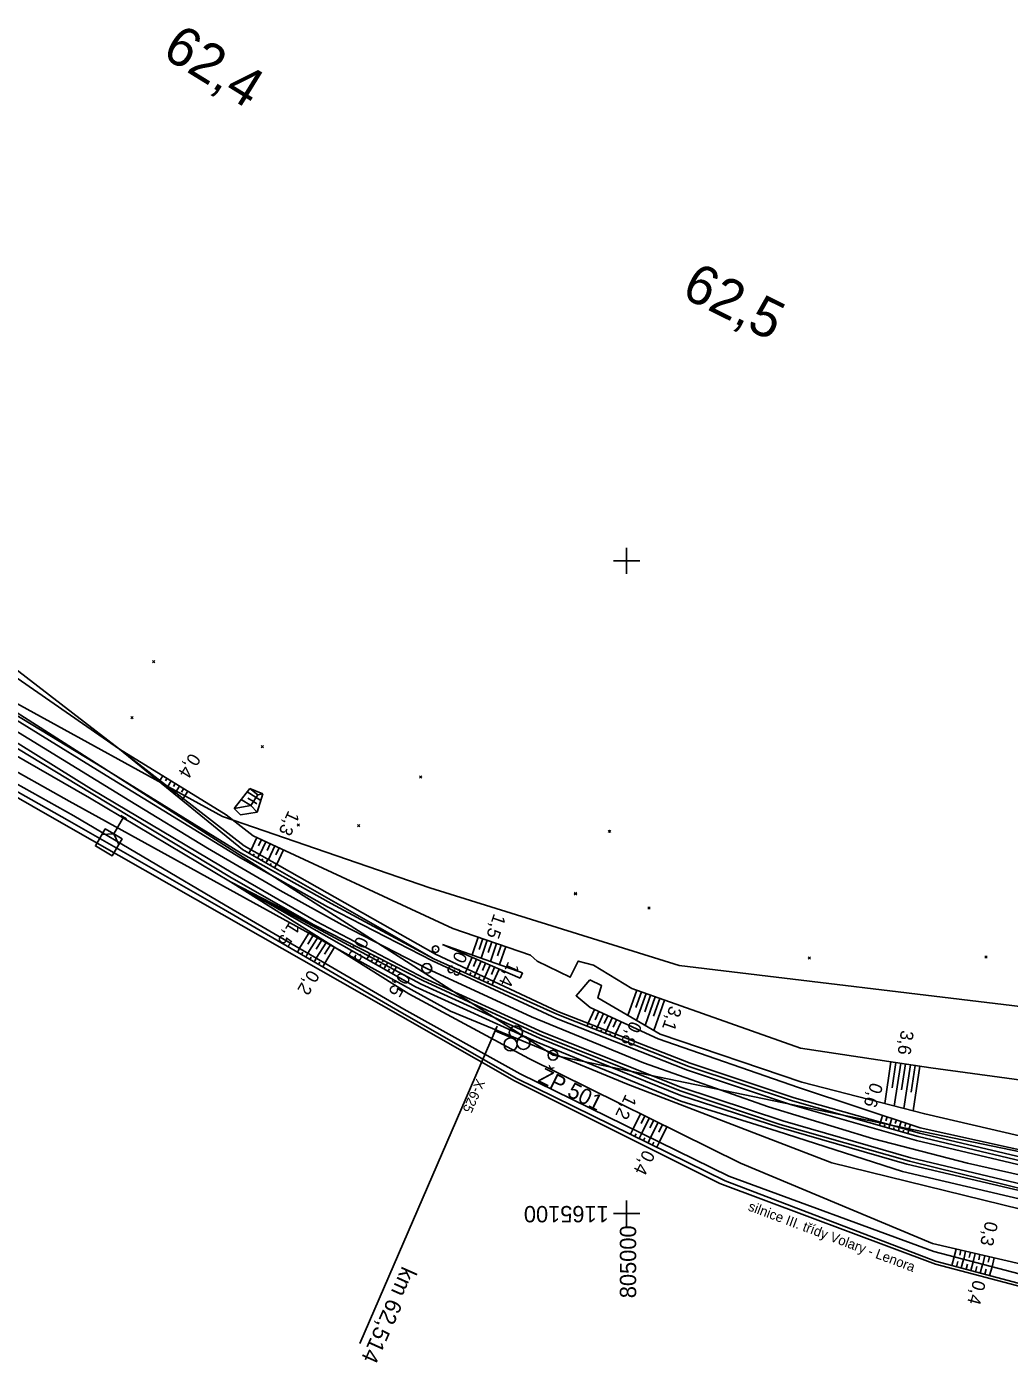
# Model space of a CAD drawing. Extents: x -805636 to -804553, y -1165340 to -1164656.
# Drawn here: x -805092 to -804941.3, y -1165124 to -1164918.2 of the extents above; entities that cross this region are included whole.
import ezdxf

# ---------------------------------------------------------------- set-up
doc = ezdxf.new("R2010")
doc.units = 0
for name, color, linetype in [('0381KM061-064P - Vrstva 1', 7, 'Continuous'), ('0381KM061-064P - Vrstva 4', 7, 'Continuous'), ('0381KM061-064P - Vrstva 48', 7, 'Continuous'), ('0381KM061-064P - Vrstva 49', 7, 'Continuous'), ('0381KM061-064P - Vrstva 51', 7, 'Continuous'), ('0381KM061-064P - Vrstva 7', 7, 'Continuous'), ('0381KM061-064P - Vrstva 8', 7, 'Continuous'), ('hran DP - hran DP', 7, 'Continuous'), ('krizky_1000 - souradnice', 7, 'Continuous'), ('krizky_1000 - Vrstva 1', 7, 'Continuous'), ('vyt_sit - polygon', 7, 'Continuous'), ('vyt_sit - stávající', 7, 'Continuous')]:
    doc.layers.add(name, color=color, linetype=linetype)

msp = doc.modelspace()

# ---------------------------------------------------------------- linework, layer by layer
at = {"layer": '0381KM061-064P - Vrstva 1'}
for points in [[(-805131.47, -1165002.7), (-805117.01, -1165011.6), (-805094.55, -1165025.46), (-805076.19, -1165036.77)], [(-805076.19, -1165036.77), (-805064.24, -1165044.04), (-805053.13, -1165050.53)], [(-805053.13, -1165050.53), (-805043.64, -1165055.76), (-805030.64, -1165062.45), (-805014.61, -1165069.88), (-804997.39, -1165076.92), (-804978.26, -1165083.66), (-804962.13, -1165088.54), (-804947.73, -1165092.28), (-804936.17, -1165094.91), (-804922.95, -1165097.46), (-804911.85, -1165099.22)]]:
    msp.add_lwpolyline(points, dxfattribs=at)
at = {"layer": '0381KM061-064P - Vrstva 4'}
for points in [[(-805257.4, -1164945.18), (-805227.5, -1164957.9), (-805205.55, -1164967.2), (-805161.7, -1164987.26), (-805121.4, -1165011.84), (-805082.08, -1165035.58)], [(-805257.21, -1164944.39), (-805227.21, -1164957.06), (-805205.17, -1164966.48), (-805161.59, -1164986.72), (-805120.84, -1165010.88), (-805082.03, -1165034.98)], [(-805187.57, -1164970.92), (-805160.12, -1164984.24), (-805119.58, -1165008.37), (-805080.47, -1165032.5)], [(-805187.4, -1164970.45), (-805159.98, -1164983.82), (-805119.44, -1165007.96), (-805080.11, -1165031.8)], [(-805080.11, -1165031.8), (-805059.18, -1165044.72), (-805045.31, -1165052.51), (-805029.54, -1165060.96), (-805010.72, -1165069.47), (-804990.45, -1165077.48), (-804974.57, -1165082.73), (-804955.28, -1165088.2), (-804932.96, -1165093.51), (-804912.39, -1165097.1), (-804892.28, -1165099.85)], [(-805080.47, -1165032.5), (-805059.19, -1165045.48), (-805045.86, -1165053.03), (-805029.76, -1165061.31), (-805010.76, -1165070.1), (-804990.66, -1165078.03), (-804974.85, -1165083.28), (-804955.57, -1165088.82), (-804933.31, -1165094.09), (-804912.36, -1165097.73), (-804892.37, -1165100.24)], [(-805082.08, -1165035.58), (-805060.58, -1165048.58), (-805047.98, -1165055.77), (-805031.23, -1165064.28), (-805013.07, -1165072.73), (-804991.62, -1165081.24), (-804976.47, -1165086.37), (-804956.64, -1165091.96), (-804934.05, -1165097.54), (-804913.13, -1165101.06), (-804892.22, -1165103.81)], [(-805082.03, -1165034.98), (-805060.37, -1165047.85), (-805047.54, -1165055.28), (-805031.06, -1165063.92), (-805012.89, -1165072.24), (-804991.69, -1165080.62), (-804976.05, -1165085.82), (-804956.42, -1165091.49), (-804933.87, -1165096.82), (-804912.82, -1165100.43), (-804892.24, -1165103.28)]]:
    msp.add_lwpolyline(points, dxfattribs=at)
at = {"layer": '0381KM061-064P - Vrstva 48'}
for p, q in [((-805071.7, -1165033.78), (-805071.58, -1165033.63)), ((-805071.12, -1165032.94), (-805071.56, -1165033.64)), ((-805070.48, -1165033.33), (-805070.72, -1165033.72)), ((-805069.84, -1165033.72), (-805070.36, -1165034.57)), ((-805071.12, -1165034.26), (-805071.05, -1165034.17)), ((-805070.54, -1165034.73), (-805070.39, -1165034.55)), ((-805069.96, -1165035.21), (-805069.88, -1165035.11)), ((-805069.21, -1165034.12), (-805069.49, -1165034.57)), ((-805069.38, -1165035.68), (-805069.2, -1165035.47)), ((-805068.57, -1165034.51), (-805069.17, -1165035.49)), ((-805067.93, -1165034.91), (-805068.25, -1165035.43)), ((-805067.29, -1165035.3), (-805067.98, -1165036.41)), ((-805058.16, -1165035.39), (-805056.82, -1165036.27)), ((-805068.8, -1165036.16), (-805068.71, -1165036.04)), ((-805068.22, -1165036.63), (-805068.02, -1165036.38)), ((-805059.08, -1165036.56), (-805057.62, -1165037.51)), ((-805058.06, -1165036.34), (-805057.22, -1165036.89)), ((-805056.69, -1165037.24), (-805057.22, -1165036.89)), ((-805056.11, -1165036.74), (-805056.82, -1165036.27)), ((-805056.69, -1165042.41), (-805057.55, -1165044.27)), ((-805056.01, -1165042.72), (-805056.45, -1165043.68)), ((-805055.32, -1165043.04), (-805056.24, -1165045.01)), ((-805054.64, -1165043.35), (-805055.11, -1165044.37)), ((-805053.96, -1165043.67), (-805054.93, -1165045.76)), ((-805053.28, -1165043.99), (-805053.78, -1165045.05)), ((-805057.91, -1165044.8), (-805057.59, -1165044.25)), ((-805057.26, -1165045.18), (-805057.1, -1165044.9)), ((-805056.61, -1165045.55), (-805056.29, -1165044.99)), ((-805055.96, -1165045.92), (-805055.8, -1165045.64)), ((-805055.31, -1165046.29), (-805054.98, -1165045.72)), ((-805052.6, -1165044.3), (-805053.62, -1165046.5)), ((-805054.65, -1165046.66), (-805054.49, -1165046.38)), ((-805054, -1165047.03), (-805053.68, -1165046.46)), ((-805050.18, -1165059.36), (-805048.58, -1165056.81)), ((-805048.9, -1165058.73), (-805047.94, -1165057.21)), ((-805048.89, -1165060.12), (-805047.31, -1165057.61)), ((-805047.61, -1165059.5), (-805046.68, -1165058.01)), ((-805047.59, -1165060.88), (-805046.04, -1165058.41)), ((-805023.71, -1165060.37), (-805022.78, -1165057.65)), ((-805022.63, -1165059.53), (-805022.07, -1165057.89)), ((-805022.3, -1165060.87), (-805021.36, -1165058.14)), ((-805021.22, -1165060.02), (-805020.66, -1165058.38)), ((-805020.89, -1165061.37), (-805019.95, -1165058.62)), ((-805050.16, -1165059.38), (-805050.49, -1165059.95)), ((-805049.64, -1165059.98), (-805049.84, -1165060.32)), ((-805048.86, -1165060.13), (-805049.19, -1165060.7)), ((-805046.33, -1165060.28), (-805045.41, -1165058.81)), ((-805046.29, -1165061.63), (-805044.77, -1165059.21)), ((-805039.53, -1165060.53), (-805039.82, -1165061.03)), ((-805039.51, -1165060.54), (-805039.32, -1165060.17)), ((-805038.77, -1165060.74), (-805038.65, -1165060.51)), ((-805019.81, -1165060.52), (-805019.24, -1165058.87)), ((-805019.48, -1165061.86), (-805018.53, -1165059.11)), ((-805048.35, -1165060.74), (-805048.55, -1165061.08)), ((-805047.57, -1165060.89), (-805047.9, -1165061.46)), ((-805047.05, -1165061.49), (-805047.25, -1165061.83)), ((-805046.27, -1165061.65), (-805046.6, -1165062.21)), ((-805038.99, -1165061.09), (-805039.17, -1165061.4)), ((-805038.21, -1165061.24), (-805038.52, -1165061.77)), ((-805038.18, -1165061.25), (-805037.98, -1165060.85)), ((-805037.68, -1165061.81), (-805037.86, -1165062.14)), ((-805037.44, -1165061.44), (-805037.31, -1165061.19)), ((-805036.89, -1165061.95), (-805037.21, -1165062.51)), ((-805036.86, -1165061.96), (-805036.64, -1165061.53)), ((-805036.36, -1165062.53), (-805036.56, -1165062.88)), ((-805036.11, -1165062.14), (-805035.97, -1165061.87)), ((-805035.57, -1165062.66), (-805035.91, -1165063.25)), ((-805035.54, -1165062.67), (-805035.3, -1165062.21)), ((-805024.47, -1165062.52), (-805024.74, -1165063.13)), ((-805024.46, -1165062.53), (-805023.69, -1165060.75)), ((-805023.47, -1165062.13), (-805023, -1165061.05)), ((-805023.1, -1165063.16), (-805022.31, -1165061.35)), ((-805022.1, -1165062.75), (-805021.62, -1165061.65)), ((-805021.74, -1165063.8), (-805020.94, -1165061.95)), ((-805020.74, -1165063.37), (-805020.25, -1165062.25)), ((-805020.39, -1165064.44), (-805019.56, -1165062.55)), ((-805023.9, -1165063.08), (-805024.06, -1165063.44)), ((-805023.11, -1165063.16), (-805023.37, -1165063.75)), ((-805022.53, -1165063.71), (-805022.69, -1165064.05)), ((-805021.75, -1165063.79), (-805022.01, -1165064.36)), ((-805021.17, -1165064.34), (-805021.32, -1165064.67)), ((-805020.39, -1165064.43), (-805020.64, -1165064.98)), ((-804999.81, -1165069.65), (-804998.44, -1165065.79)), ((-804998.58, -1165068.43), (-804997.73, -1165066.04)), ((-804998.48, -1165070.41), (-804997.03, -1165066.29)), ((-804997.22, -1165069.09), (-804996.32, -1165066.54)), ((-804997.16, -1165071.17), (-804995.61, -1165066.79)), ((-805005.89, -1165070.86), (-805004.93, -1165068.76)), ((-804995.86, -1165069.75), (-804994.91, -1165067.04)), ((-804995.84, -1165071.94), (-804994.2, -1165067.29)), ((-805005.88, -1165070.86), (-805006.06, -1165071.31)), ((-805004.81, -1165070.31), (-805004.25, -1165069.07)), ((-805004.49, -1165071.4), (-805003.57, -1165069.38)), ((-805003.43, -1165070.88), (-805002.89, -1165069.69)), ((-805003.1, -1165071.95), (-805002.21, -1165070)), ((-805002.05, -1165071.46), (-805001.53, -1165070.31)), ((-805001.7, -1165072.49), (-805000.85, -1165070.62)), ((-805005.26, -1165071.31), (-805005.36, -1165071.58)), ((-805004.49, -1165071.41), (-805004.67, -1165071.86)), ((-805003.86, -1165071.86), (-805003.97, -1165072.13)), ((-805003.09, -1165071.95), (-805003.27, -1165072.41)), ((-805002.46, -1165072.41), (-805002.57, -1165072.68)), ((-805001.69, -1165072.5), (-805001.88, -1165072.96)), ((-804960.43, -1165083.16), (-804959.47, -1165076.75)), ((-804959.31, -1165080.75), (-804958.72, -1165076.86)), ((-804958.97, -1165083.54), (-804957.98, -1165076.97)), ((-804957.84, -1165081.07), (-804957.24, -1165077.09)), ((-804957.51, -1165083.92), (-804956.5, -1165077.2)), ((-804956.37, -1165081.39), (-804955.76, -1165077.31)), ((-804956.05, -1165084.29), (-804955.02, -1165077.42)), ((-804997.87, -1165084.72), (-804999.02, -1165087.05)), ((-804997.2, -1165085.05), (-804997.77, -1165086.21)), ((-804996.53, -1165085.38), (-804997.68, -1165087.71)), ((-804961.1, -1165086), (-804960.76, -1165084.96)), ((-804960.24, -1165085.8), (-804960.04, -1165085.2)), ((-804999.41, -1165087.84), (-804999.02, -1165087.05)), ((-804995.85, -1165085.71), (-804996.43, -1165086.88)), ((-804995.18, -1165086.05), (-804996.33, -1165088.36)), ((-804994.51, -1165086.38), (-804995.08, -1165087.54)), ((-804993.84, -1165086.71), (-804994.98, -1165089.03)), ((-804961.08, -1165086.01), (-804961.22, -1165086.52)), ((-804960.41, -1165086.42), (-804960.5, -1165086.72)), ((-804959.63, -1165086.42), (-804959.78, -1165086.93)), ((-804959.66, -1165086.41), (-804959.33, -1165085.43)), ((-804958.97, -1165086.82), (-804959.06, -1165087.13)), ((-804958.81, -1165086.23), (-804958.62, -1165085.67)), ((-804958.19, -1165086.82), (-804958.34, -1165087.33)), ((-804958.21, -1165086.82), (-804957.91, -1165085.9)), ((-804957.53, -1165087.23), (-804957.62, -1165087.54)), ((-804957.37, -1165086.67), (-804957.2, -1165086.14)), ((-804956.75, -1165087.23), (-804956.89, -1165087.75)), ((-804956.77, -1165087.22), (-804956.48, -1165086.37)), ((-804998.73, -1165088.17), (-804998.54, -1165087.77)), ((-804998.06, -1165088.5), (-804997.67, -1165087.71)), ((-804997.39, -1165088.83), (-804997.19, -1165088.43)), ((-804996.71, -1165089.16), (-804996.32, -1165088.37)), ((-804996.04, -1165089.49), (-804995.84, -1165089.09)), ((-804995.36, -1165089.82), (-804994.98, -1165089.03)), ((-804949.77, -1165106.66), (-804949.49, -1165105.44)), ((-804948.93, -1165106.36), (-804948.76, -1165105.61)), ((-804948.32, -1165107.04), (-804948.03, -1165105.78)), ((-804947.47, -1165106.72), (-804947.29, -1165105.95)), ((-804949.79, -1165106.66), (-804950.13, -1165107.96)), ((-804949.2, -1165107.37), (-804949.41, -1165108.15)), ((-804948.34, -1165107.04), (-804948.69, -1165108.34)), ((-804947.75, -1165107.75), (-804947.96, -1165108.54)), ((-804946.89, -1165107.42), (-804947.24, -1165108.73)), ((-804946.86, -1165107.42), (-804946.56, -1165106.12)), ((-804946.02, -1165107.08), (-804945.83, -1165106.29)), ((-804945.44, -1165107.79), (-804945.79, -1165109.12)), ((-804945.41, -1165107.8), (-804945.1, -1165106.46)), ((-804944.56, -1165107.45), (-804944.37, -1165106.63)), ((-804943.96, -1165108.18), (-804943.64, -1165106.8)), ((-804946.3, -1165108.13), (-804946.51, -1165108.92)), ((-804944.85, -1165108.51), (-804945.06, -1165109.31)), ((-804943.98, -1165108.17), (-804944.34, -1165109.5))]:
    msp.add_line(p, q, dxfattribs=at)
at = {"layer": '0381KM061-064P - Vrstva 49'}
for p, q in [((-805072.34, -1165015.61), (-805072.69, -1165015.26)), ((-805072.34, -1165015.26), (-805072.69, -1165015.61)), ((-805075.64, -1165024.19), (-805076, -1165023.84)), ((-805075.64, -1165023.84), (-805076, -1165024.19)), ((-805055.69, -1165028.65), (-805056.04, -1165028.29)), ((-805055.69, -1165028.29), (-805056.04, -1165028.65)), ((-805031.42, -1165033.3), (-805031.77, -1165032.95)), ((-805031.42, -1165032.95), (-805031.77, -1165033.3)), ((-805050.15, -1165040.65), (-805050.5, -1165040.3)), ((-805050.15, -1165040.3), (-805050.5, -1165040.65)), ((-805040.91, -1165040.77), (-805041.26, -1165040.42)), ((-805040.91, -1165040.42), (-805041.26, -1165040.77)), ((-805002.45, -1165041.64), (-805002.8, -1165041.28)), ((-805002.45, -1165041.28), (-805002.8, -1165041.64)), ((-805007.66, -1165051.16), (-805008.02, -1165050.81)), ((-805007.66, -1165050.81), (-805008.02, -1165051.16)), ((-804996.38, -1165053.38), (-804996.73, -1165053.03)), ((-804996.38, -1165053.03), (-804996.73, -1165053.38)), ((-804971.83, -1165061.04), (-804972.19, -1165060.69)), ((-804971.83, -1165060.69), (-804972.19, -1165061.04)), ((-804944.72, -1165060.86), (-804945.08, -1165060.51)), ((-804944.72, -1165060.51), (-804945.08, -1165060.86)), ((-805029.54, -1165060.96), (-805010.72, -1165069.47))]:
    msp.add_line(p, q, dxfattribs=at)
for points in [[(-805254.52, -1164927.32), (-805250.48, -1164933.58), (-805239.73, -1164938.85), (-805217.98, -1164949.5), (-805160.38, -1164977.95), (-805138.64, -1164988.6), (-805110.66, -1165003.53), (-805077.76, -1165028.83)], [(-805234.27, -1164967.17), (-805220.67, -1164970.52), (-805207.94, -1164974.16), (-805191.02, -1164980.42), (-805165.29, -1164994.07), (-805122, -1165019.23), (-805085.43, -1165039.91)], [(-805234.06, -1164966.19), (-805220.55, -1164969.15), (-805207.89, -1164972.65), (-805190.88, -1164979.53), (-805164.65, -1164993.41), (-805121.85, -1165018.34), (-805084.74, -1165039.06)], [(-805205.55, -1164967.2), (-805162.48, -1164988.88), (-805121.89, -1165013.64), (-805082.35, -1165036.29)], [(-805185.93, -1164967.81), (-805156.92, -1164981.59), (-805111.71, -1165005.38), (-805077.76, -1165028.83)], [(-805077.76, -1165028.83), (-805058.62, -1165043.66), (-805029.31, -1165060.25)], [(-805077.76, -1165028.83), (-805061.41, -1165038.93), (-805057.27, -1165042.14), (-805026.66, -1165056.32), (-805014.74, -1165060.42)], [(-805077.76, -1165028.83), (-805058.9, -1165044.24), (-805029.54, -1165060.96)], [(-805060.16, -1165037.96), (-805057.76, -1165034.87)], [(-805057.76, -1165034.87), (-805055.79, -1165035.72)], [(-805056.55, -1165035.87), (-805057.76, -1165034.87)], [(-805056.55, -1165035.87), (-805057.62, -1165037.51)], [(-805056.65, -1165038.5), (-805055.79, -1165035.72)], [(-805056.55, -1165035.87), (-805055.79, -1165035.72)], [(-805082.35, -1165036.29), (-805060.73, -1165049.17)], [(-805057.62, -1165037.51), (-805060.16, -1165037.96)], [(-805060.16, -1165037.96), (-805059.18, -1165038.9), (-805056.65, -1165038.5)], [(-805057.62, -1165037.51), (-805056.65, -1165038.5)], [(-805085.43, -1165039.91), (-805061.8, -1165053.37), (-805034.45, -1165069.27), (-805016.82, -1165079.3), (-804984.87, -1165094.97), (-804952.63, -1165107.29), (-804923.66, -1165115.02), (-804890.91, -1165119.51), (-804860.93, -1165120.87), (-804821.85, -1165122.9), (-804805.33, -1165123.27)], [(-805084.74, -1165039.06), (-805061.55, -1165052.74), (-805034.17, -1165068.7), (-805016.31, -1165078.58), (-804984.31, -1165094.26), (-804952.92, -1165105.84), (-804923.4, -1165113.55), (-804890.69, -1165118.62), (-804860.79, -1165119.97), (-804821.99, -1165121.8), (-804804.98, -1165122.47)], [(-805060.73, -1165049.17), (-805031.5, -1165064.84), (-805013.36, -1165073.14), (-804991.7, -1165081.91), (-804976.67, -1165086.76), (-804957.06, -1165092.46), (-804934.14, -1165097.81), (-804913.12, -1165101.52), (-804892.37, -1165104.14)], [(-805060.73, -1165049.17), (-805032.39, -1165065.25)], [(-805060.73, -1165049.17), (-805033.41, -1165066.35)], [(-805060.73, -1165049.17), (-805047.98, -1165055.77), (-805031.23, -1165064.28), (-805013.07, -1165072.73), (-804991.62, -1165081.24), (-804976.47, -1165086.37), (-804956.64, -1165091.96), (-804934.05, -1165097.54), (-804913.13, -1165101.06), (-804892.22, -1165103.81), (-804860.51, -1165107.09), (-804841.9, -1165109.22), (-804820.58, -1165111.74), (-804811.31, -1165113.56)], [(-805029.31, -1165060.25), (-805010.57, -1165069.03), (-804990.26, -1165076.95), (-804974.29, -1165082.29), (-804955.12, -1165087.69)], [(-805028.22, -1165058.77), (-805015.98, -1165063.1)], [(-805028.22, -1165058.77), (-805016.34, -1165063.96)], [(-805014.74, -1165060.42), (-805013.72, -1165061.35), (-805008.65, -1165063.79), (-805007.41, -1165061.32), (-805005.07, -1165061.94), (-804999.18, -1165065.52), (-804973.34, -1165074.67), (-804953.36, -1165077.67), (-804930.03, -1165080.86)], [(-805016.34, -1165063.96), (-805015.98, -1165063.1)], [(-805005.66, -1165064.21), (-805007.76, -1165066.63), (-805005.59, -1165068.46), (-804995.17, -1165073.22)], [(-805005.66, -1165064.21), (-805003.85, -1165065.08), (-805004.43, -1165066.97), (-804994.86, -1165072.51)], [(-805033.41, -1165066.35), (-805014.98, -1165076.25), (-804982.53, -1165092.31), (-804953.12, -1165104.6), (-804922.96, -1165111.59), (-804890.43, -1165117.32), (-804859.92, -1165117.39), (-804821.94, -1165119.94), (-804804.42, -1165121.15)], [(-805032.39, -1165065.25), (-805013.72, -1165073.73), (-804991.69, -1165082.79), (-804976.92, -1165087.4), (-804957.71, -1165093.59), (-804934.8, -1165098.93), (-804913.68, -1165102.56), (-804892.44, -1165105.41)], [(-805010.72, -1165069.47), (-804990.45, -1165077.48), (-804974.57, -1165082.73), (-804955.28, -1165088.2), (-804932.96, -1165093.51), (-804912.39, -1165097.1), (-804892.28, -1165099.85), (-804859.81, -1165103.25), (-804840.34, -1165105.46), (-804819.52, -1165107.92), (-804802.69, -1165109.64), (-804799.68, -1165110)], [(-804994.86, -1165072.51), (-804973.16, -1165079.86), (-804954.29, -1165084.75), (-804932.5, -1165089.79), (-804920.22, -1165090.5), (-804911.77, -1165084.22), (-804893.29, -1165083.05), (-804876.57, -1165085.04), (-804853.44, -1165091.21), (-804839.72, -1165094.63), (-804814.35, -1165098.18)], [(-804995.17, -1165073.22), (-804973.67, -1165080.7), (-804954.98, -1165086.86), (-804932.57, -1165091.85), (-804911.87, -1165094.85)], [(-804955.12, -1165087.69), (-804932.8, -1165092.95), (-804911.98, -1165096.48), (-804892.31, -1165098.96)]]:
    msp.add_lwpolyline(points, dxfattribs=at)
at = {"layer": '0381KM061-064P - Vrstva 51'}
for points in [[(-805234.38, -1164968.09), (-805220.73, -1164971.11), (-805207.78, -1164974.89), (-805191.18, -1164980.95), (-805165.61, -1164994.58), (-805122.14, -1165019.85), (-805085.93, -1165040.55)], [(-805085.93, -1165040.55), (-805062.08, -1165054.12), (-805034.69, -1165069.73), (-805017.21, -1165079.65), (-804985.71, -1165095.39), (-804952.66, -1165107.75), (-804923.93, -1165115.31), (-804890.75, -1165120.1), (-804861.18, -1165121.85), (-804821.92, -1165123.67), (-804805.64, -1165124)]]:
    msp.add_lwpolyline(points, dxfattribs=at)
at = {"layer": '0381KM061-064P - Vrstva 7'}
for p, q in [((-805078.64, -1165041.84), (-805077.12, -1165039.26)), ((-805076.69, -1165039.51), (-805077.56, -1165039)), ((-805029.33, -1165059.48), (-805029.24, -1165059.53))]:
    msp.add_line(p, q, dxfattribs=at)
for points in [[(-805078.64, -1165041.84), (-805079.94, -1165041.08), (-805081.46, -1165043.67), (-805078.87, -1165045.19), (-805077.35, -1165042.6), (-805078.64, -1165041.84)], [(-805077.86, -1165043.47), (-805078.64, -1165041.84), (-805080.45, -1165041.95)]]:
    msp.add_lwpolyline(points, dxfattribs=at)
for centre, radius in [((-805029.29, -1165059.51), 0.5), ((-805030.64, -1165062.45), 0.75)]:
    msp.add_circle(centre, radius, dxfattribs=at)
at = {"layer": '0381KM061-064P - Vrstva 8'}
for p, q in [((-805020.14, -1165071.99), (-805040.91, -1165119.94)), ((-805019.84, -1165071.3), (-805020.44, -1165072.67)), ((-805020.14, -1165071.99), (-805017.39, -1165073.18))]:
    msp.add_line(p, q, dxfattribs=at)
for centre in [(-805016.99, -1165072.26), (-805015.83, -1165073.86), (-805017.79, -1165074.1)]:
    msp.add_circle(centre, 1, dxfattribs=at)
at = {"layer": 'hran DP - hran DP'}
for p, q in [((-805100.45, -1165018.04), (-805061.96, -1165039.19)), ((-805085.48, -1165036.81), (-805115.56, -1165019.91)), ((-805027.03, -1165069.02), (-805085.48, -1165036.81)), ((-805061.96, -1165039.19), (-805030.17, -1165050.11)), ((-805030.17, -1165050.11), (-804991.93, -1165061.99)), ((-804991.93, -1165061.99), (-804883.1, -1165075.15)), ((-804999.74, -1165080.26), (-805027.03, -1165069.02)), ((-804968.55, -1165092.26), (-804999.74, -1165080.26)), ((-804934.32, -1165100.62), (-804968.55, -1165092.26))]:
    msp.add_line(p, q, dxfattribs=at)
at = {"layer": 'krizky_1000 - Vrstva 1'}
for points in [[(-805000, -1164998), (-805000, -1165002)], [(-805002, -1165000), (-804998, -1165000)], [(-805000, -1165098), (-805000, -1165102)], [(-805002, -1165100), (-804998, -1165100)]]:
    msp.add_lwpolyline(points, dxfattribs=at)
at = {"layer": 'vyt_sit - polygon'}
for p, q in [((-805011.29, -1165075.75), (-805156.24, -1164983.18)), ((-804836.52, -1165111.83), (-805011.29, -1165075.75))]:
    msp.add_line(p, q, dxfattribs=at)
at = {"layer": 'vyt_sit - stávající'}
msp.add_line((-805011.33, -1165075.72), (-805011.24, -1165075.78), dxfattribs=at)
msp.add_circle((-805011.29, -1165075.75), 0.756, dxfattribs=at)

# ---------------------------------------------------------------- texts
at = {"layer": '0381KM061-064P - Vrstva 48'}
for s, rotation, p in [('0,4', 238.304, (-805066.88, -1165029.32)), ('1,3', 245.1485, (-805051.84, -1165038.14)), ('1,5', 251.0215, (-805020.34, -1165053.96)), ('1,5', 237.8283, (-805051.65, -1165055.14)), ('0,3', 245.683, (-805041.29, -1165057.41)), ('0,3', 245.683, (-805026.16, -1165059.68)), ('1,4', 246.405, (-805018.15, -1165061.28)), ('0,2', 239.8249, (-805048.7, -1165062.53)), ('0,5', 240.4291, (-805034.77, -1165062.85)), ('3,1', 250.5147, (-804993.36, -1165068.06)), ('0,8', 245.4289, (-804999.39, -1165070.38)), ('3,6', 261.4565, (-804957.92, -1165071.85)), ('0,6', 251.7483, (-804962.54, -1165079.81)), ('1,2', 243.6728, (-805000.13, -1165081.62)), ('0,4', 243.8879, (-804997.36, -1165090.12)), ('0,3', 256.9445, (-804944.98, -1165101.08)), ('0,4', 255.0624, (-804946.83, -1165110.07))]:
    msp.add_text(s, height=2, rotation=rotation, dxfattribs=at).set_placement(p)
at = {"layer": '0381KM061-064P - Vrstva 51'}
msp.add_text('silnice III. třídy Volary - Lenora', height=1.5, rotation=339.5082, dxfattribs=at).set_placement((-804981.49, -1165099.49))
at = {"layer": '0381KM061-064P - Vrstva 7'}
for s, rotation, p in [('62,4', 328.3477, (-805071.45, -1164922.62)), ('62,5', 333.6639, (-804991.8, -1164959.45))]:
    msp.add_text(s, height=6, rotation=rotation, dxfattribs=at).set_placement(p)
at = {"layer": '0381KM061-064P - Vrstva 8'}
for s, height, rotation, p in [('X-625', 1.5, 246.0395, (-805023.02, -1165079.26)), ('km 62,514', 2.5, 245.9676, (-805034.38, -1165107.96))]:
    msp.add_text(s, height=height, rotation=rotation, dxfattribs=at).set_placement(p)
at = {"layer": 'krizky_1000 - souradnice'}
for s, rotation, p in [('1165100', 180, (-805002.74, -1165098.85)), ('805000', 90, (-804998.54, -1165112.98))]:
    msp.add_text(s, height=2.5, rotation=rotation, dxfattribs=at).set_placement(p)
at = {"layer": 'vyt_sit - stávající'}
msp.add_text('ŽP 501', height=2.4, rotation=333.5611, dxfattribs=at).set_placement((-805013.74, -1165079.72))

doc.saveas('drawing.dxf')
